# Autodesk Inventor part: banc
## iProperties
Shininess: 64.0
Length Units: 11269
Angle Units: 11279
Time Units: 11290
Mass Units: 11283
Length Display Precision: 3
Angle Display Precision: 2
Compacted: True
Part Number: banc
Document SubType Name: Modeling
Created: 2004-06
Material: Par défaut
Designer: David
Density: 0.0
Volumn: 0.0
Area: 0.0
PropertySet Name: Model Information
Control State: 0
Master: False
Checked Out: False
Author: David
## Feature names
1. Extrusion1
2. Perçage1 [Hole]
3. Extrusion2
4. Perçage2 [Hole]
5. Congé1 [Fillet]
6. Perçage3 [Hole]
7. Congé2 [Fillet]
